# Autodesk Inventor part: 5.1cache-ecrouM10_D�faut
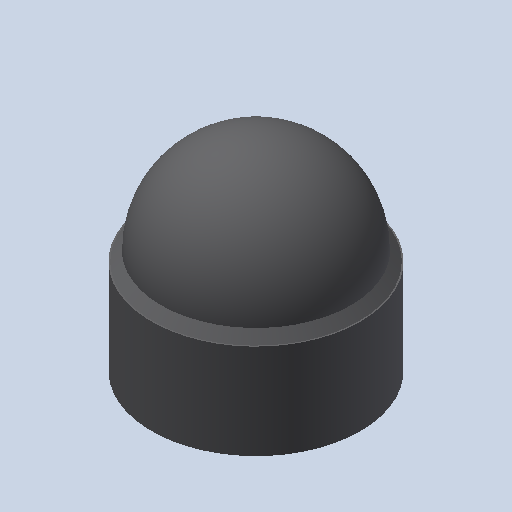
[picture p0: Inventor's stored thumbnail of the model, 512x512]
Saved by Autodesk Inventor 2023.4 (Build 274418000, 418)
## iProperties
Created: 2011-01
Part Number: 5.1cache-ecrouM10_D�faut
Document SubType Name: Modeling
Designer: eric
Density: 1 g/cm^3
Mass: 2.7477 g
Surface Area: 26.0068 cm^2
Volume: 2.7477 cm^3
Material: Générique
Appearance: Red
Author: eric
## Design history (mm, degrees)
feature "Base1"
node "Corps solides"
node "Corps surfaciques"
node "Solide1"
